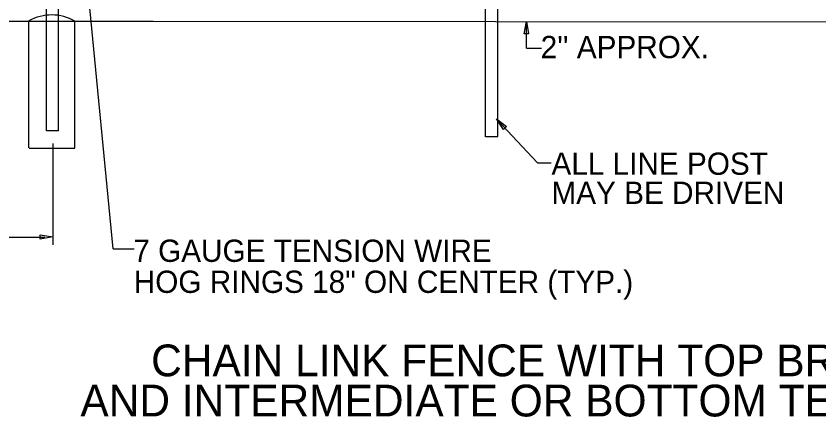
# Model space of a CAD drawing. Extents: x 0 to 1270, y 0 to 830.
# Drawn here: x 239.1 to 416.1, y 290.8 to 379.1 of the extents above; entities that cross this region are included whole.
import ezdxf

# ---------------------------------------------------------------- set-up
doc = ezdxf.new("R2010")
doc.units = 0
for name, color, linetype in [('CT_CSHT_GeneralLabel', 7, 'Continuous'), ('CT_Dimensions', 7, 'Continuous'), ('sb_Chainlink Fence', 7, 'Continuous'), ('sb_Existing Concrete', 7, 'Continuous'), ('sb_Existing Structural Steel', 7, 'Continuous')]:
    doc.layers.add(name, color=color, linetype=linetype)

msp = doc.modelspace()

# ---------------------------------------------------------------- linework, layer by layer
at = {"layer": 'CT_Dimensions'}
for p, q in [((260.56, 327.82), (255.05, 384.12)), ((351.62, 371.99), (351.62, 377.42)), ((351.62, 371.99), (354.99, 371.97)), ((345.21, 356.25), (354.06, 346.76)), ((342.63, 352.53), (345.32, 352.53)), ((247.19, 351.01), (247.19, 328.69)), ((354.06, 346.76), (357.1, 346.76)), ((53.69, 330.39), (245.46, 330.39)), ((260.56, 327.82), (265.19, 327.82))]:
    msp.add_line(p, q, dxfattribs=at)
for points in [[(351.16, 375.15), (351.62, 377.9), (352.08, 375.15)], [(346.55, 354.12), (345.05, 356.46), (347.23, 354.73)], [(244.47, 330.89), (247.22, 330.43), (244.47, 329.97)]]:
    msp.add_lwpolyline(points, close=True, dxfattribs=at)
at = {"layer": 'sb_Chainlink Fence'}
for p, q in [((56.28, 378.13), (269.33, 377.94)), ((269.33, 377.94), (459.11, 377.79))]:
    msp.add_line(p, q, dxfattribs=at)
at = {"layer": 'sb_Existing Concrete'}
for p, q in [((241.96, 350.06), (241.96, 377.97)), ((252.08, 350.04), (252.08, 377.94)), ((242.01, 350.01), (252.1, 350.01))]:
    msp.add_line(p, q, dxfattribs=at)
msp.add_arc((246.99, 369.17), 10.15, 59.953, 119.6876, dxfattribs=at)
at = {"layer": 'sb_Existing Structural Steel'}
for p, q in [((245.82, 378.95), (245.86, 432.27)), ((248.51, 378.92), (248.56, 432.37)), ((342.6, 377.86), (342.65, 432.56)), ((345.31, 377.93), (345.36, 432.65)), ((245.81, 353.79), (245.82, 378.95)), ((248.51, 353.77), (248.51, 378.92)), ((342.6, 352.5), (342.6, 377.86)), ((345.31, 352.58), (345.31, 377.93)), ((248.51, 353.77), (245.83, 353.77))]:
    msp.add_line(p, q, dxfattribs=at)

# ---------------------------------------------------------------- texts
at = {"layer": 'CT_CSHT_GeneralLabel'}
for s, p in [('CHAIN LINK FENCE WITH TOP BRACE RAIL', (268.9, 299.76)), ('AND INTERMEDIATE OR BOTTOM TENSION WIRE', (253.3, 290.92))]:
    msp.add_text(s, height=7, dxfattribs=at).set_placement(p)
at = {"layer": 'CT_Dimensions'}
for s, p in [("2'' APPROX.", (354.77, 369.8)), ('ALL LINE POST', (357.15, 344.12)), ('MAY BE DRIVEN', (357.15, 337.71)), ('7 GAUGE TENSION WIRE', (264.97, 324.95)), ('HOG RINGS 18" ON CENTER (TYP.)', (265.07, 318.12))]:
    msp.add_text(s, height=4.9005, dxfattribs=at).set_placement(p)

doc.saveas('drawing.dxf')
